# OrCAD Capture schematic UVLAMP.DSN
size A; title: UVLamp - SRO2003; rev: V1.0; note: MEZIERE Fabien - https://www.instructables.com/member/-SRO2-/
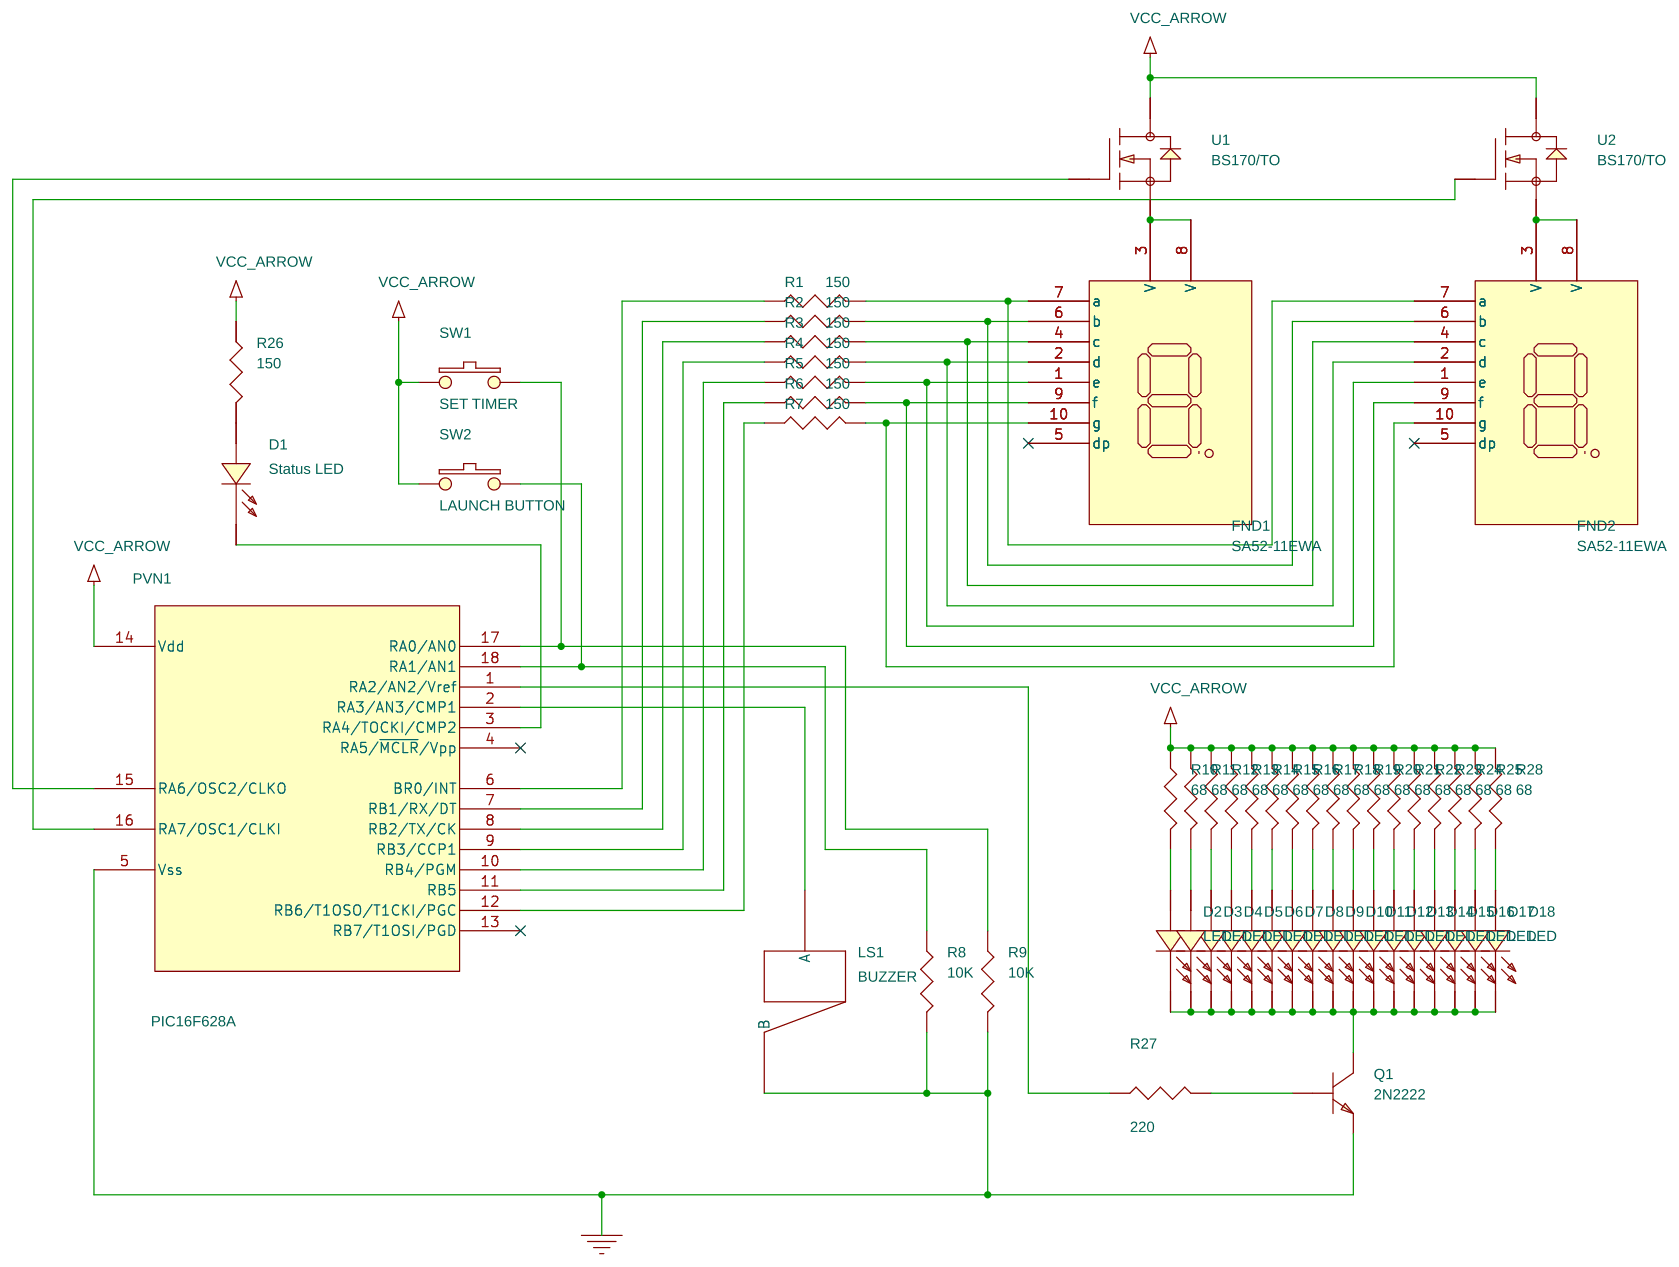
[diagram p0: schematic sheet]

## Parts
D1  Status LED
D2  LED
D3  LED
D4  LED
D5  LED
D6  LED
D7  LED
D8  LED
D9  LED
D10  LED
D11  LED
D12  LED
D13  LED
D14  LED
D15  LED
D16  LED
D17  LED
D18  LED
FND1  SA52-11EWA
FND2  SA52-11EWA
LS1  BUZZER
PVN1  PIC16F628A
Q1  2N2222
R1  150
R2  150
R3  150
R4  150
R5  150
R6  150
R7  150
R8  10K
R9  10K
R10  68
R11  68
R12  68
R13  68
R14  68
R15  68
R16  68
R17  68
R18  68
R19  68
R20  68
R21  68
R22  68
R23  68
R24  68
R25  68
R26  150
R27  220
R28  68
SW1  SET TIMER
SW2  LAUNCH BUTTON
U1  BS170/TO
U2  BS170/TO

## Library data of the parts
D1-D18 = LED
FND1 FND2 = 5163ASR_1
LS1 = BUZZER
PVN1 = PIC16F628A
Q1 = 2N2222
R1-R28 = R
SW1 SW2 = SW_PB_SPST
U1 U2 = BS170_TO

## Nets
GND: LS1.2(B) PVN1.5(Vss) Q1.1(EMITTER) R8.2 R9.2
VCC_ARROW: PVN1.14(Vdd) R10.1 R11.1 R12.1 R13.1 R14.1 R15.1 R16.1 R17.1 R18.1 R19.1 R20.1 R21.1 R22.1 R23.1 R24.1 R25.1 R26.1 R28.1 SW1.1 SW2.1 U1.1(D) U2.1(D)
N01111: FND1.7(a) FND2.7(a) R1.2
N01115: FND1.6(b) FND2.6(b) R2.2
N01121: FND1.4(c) FND2.4(c) R3.2
N01125: FND1.2(d) FND2.2(d) R4.2
N01129: FND1.1(e) FND2.1(e) R5.2
N01133: FND1.9(f) FND2.9(f) R6.2
N01137: FND1.10(g) FND2.10(g) R7.2
N02373: PVN1.6(BR0/INT) R1.1
N02385: PVN1.7(RB1/RX/DT) R2.1
N02397: PVN1.8(RB2/TX/CK) R3.1
N02409: PVN1.9(RB3/CCP1) R4.1
N02421: PVN1.10(RB4/PGM) R5.1
N02537: PVN1.11(RB5) R6.1
N02549: PVN1.12(RB6/T1OSO/T1CKI/PGC) R7.1
N02949: LS1.1(A) PVN1.2(RA3/AN3/CMP1)
N03210: PVN1.17(RA0/AN0) R9.1 SW1.2
N03222: PVN1.18(RA1/AN1) R8.1 SW2.2
N03906: PVN1.15(RA6/OSC2/CLKO) U1.2(G)
N03918: PVN1.16(RA7/OSC1/CLKI) U2.2(G)
N04735: D2.1(ANODE) R10.2
N04739: D3.1(ANODE) R11.2
N04743: D4.1(ANODE) R12.2
N04747: D5.1(ANODE) R13.2
N04751: D6.1(ANODE) R14.2
N04755: D7.1(ANODE) R15.2
N04759: D8.1(ANODE) R16.2
N04763: D9.1(ANODE) R17.2
N04767: D10.1(ANODE) R18.2
N04771: D11.1(ANODE) R19.2
N04775: D12.1(ANODE) R20.2
N04779: D13.1(ANODE) R21.2
N04783: D14.1(ANODE) R22.2
N04787: D15.1(ANODE) R23.2
N04791: D16.1(ANODE) R24.2
N04795: D17.1(ANODE) R25.2
N04828: D2.2(CATHODE) D3.2(CATHODE) D4.2(CATHODE) D5.2(CATHODE) D6.2(CATHODE) D7.2(CATHODE) D8.2(CATHODE) D9.2(CATHODE) D10.2(CATHODE) D11.2(CATHODE) D12.2(CATHODE) D13.2(CATHODE) D14.2(CATHODE) D15.2(CATHODE) D16.2(CATHODE) D17.2(CATHODE) D18.2(CATHODE) Q1.3(COLLECTOR)
N04921: PVN1.1(RA2/AN2/Vref) R27.1
N06036: D1.2(CATHODE) PVN1.3(RA4/TOCKI/CMP2)
N08745: Q1.2(BASE) R27.2
N09722: FND1.3(V) FND1.8(V) U1.3(S)
N09726: FND2.3(V) FND2.8(V) U2.3(S)
N09997: D1.1(ANODE) R26.2
N10236: D18.1(ANODE) R28.2

Not connected (* = marked no-connect by the designer): FND1 5(dp)*; FND2 5(dp)*; PVN1 4(RA5/~{MCLR}/Vpp)* 13(RB7/T1OSI/PGD)*
